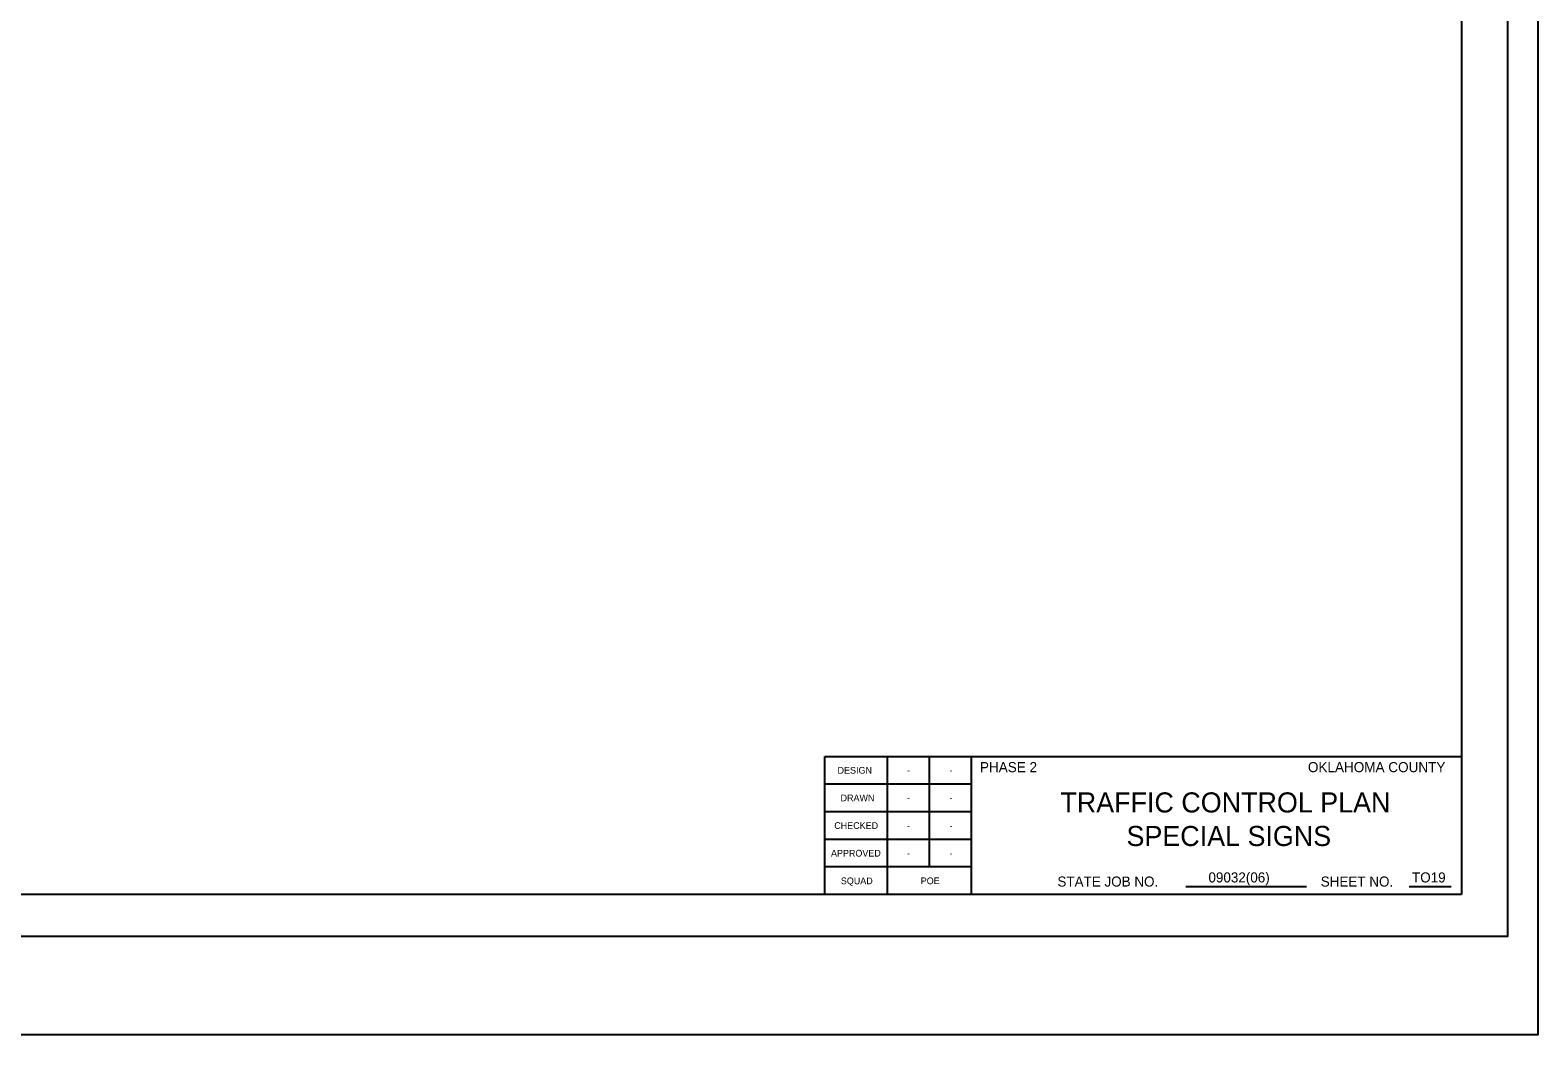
# Model space of a CAD drawing. Extents: x -434 to 1366, y -662 to 538.
# Drawn here: x 466 to 1366, y -662 to -62 of the extents above; entities that cross this region are included whole.
import ezdxf

# ---------------------------------------------------------------- set-up
doc = ezdxf.new("R2010")
doc.units = 0
for name, color, linetype in [('SHT_Plot_Shape_Full', 7, 'Continuous'), ('SHT_Plot_Shape_Half', 7, 'Continuous'), ('SHT_Sheet_Border', 7, 'Continuous'), ('SHT_Standard_Sheet_Lines', 7, 'Continuous'), ('SHT_Standard_Sheet_Txt', 7, 'Continuous')]:
    doc.layers.add(name, color=color, linetype=linetype)

msp = doc.modelspace()

# ---------------------------------------------------------------- linework, layer by layer
at = {"layer": 'SHT_Plot_Shape_Full'}
msp.add_lwpolyline([(-433.98, 538.27), (1366.02, 538.27), (1366.02, -661.73), (-433.98, -661.73)], close=True, dxfattribs=at)
at = {"layer": 'SHT_Plot_Shape_Half'}
msp.add_lwpolyline([(-352.1, 497.02), (1347.9, 497.02), (1347.9, -602.98), (-352.1, -602.98)], close=True, dxfattribs=at)
at = {"layer": 'SHT_Sheet_Border'}
for p, q in [((940.4, -495.48), (1320.4, -495.47)), ((940.4, -577.98), (940.4, -495.48)), ((1027.89, -577.98), (1027.89, -495.44))]:
    msp.add_line(p, q, dxfattribs=at)
msp.add_lwpolyline([(1320.4, -577.98), (-254.6, -577.98), (-254.6, 472.02), (1320.4, 472.02)], close=True, dxfattribs=at)
at = {"layer": 'SHT_Standard_Sheet_Lines'}
for p, q in [((977.9, -577.98), (977.9, -495.44)), ((1002.89, -561.47), (1002.89, -495.44)), ((1155.93, -573.17), (1227.95, -573.17)), ((1289.17, -573.17), (1314.29, -573.17))]:
    msp.add_line(p, q, dxfattribs=at)
for points in [[(1027.89, -511.98), (940.4, -511.98)], [(1027.89, -528.48), (940.4, -528.48)], [(1027.89, -544.98), (940.4, -544.98)], [(1027.89, -561.48), (940.4, -561.48)]]:
    msp.add_lwpolyline(points, dxfattribs=at)

# ---------------------------------------------------------------- texts
at = {"layer": 'SHT_Standard_Sheet_Txt'}
for s, height, p in [('DESIGN', 4, (948.01, -505.73)), ('-', 4, (989.42, -505.71)), ('-', 4, (1014.84, -505.71)), ('DRAWN', 4, (949.8, -522.23)), ('-', 4, (989.42, -522.21)), ('-', 4, (1014.84, -522.21)), ('TRAFFIC CONTROL PLAN', 12, (1081, -528.93)), ('CHECKED', 4, (946.04, -538.74)), ('-', 4, (989.42, -538.72)), ('-', 4, (1014.84, -538.72)), ('SPECIAL SIGNS', 12, (1120.47, -548.97)), ('APPROVED', 4, (944.08, -555.25)), ('-', 4, (989.42, -555.23)), ('-', 4, (1014.84, -555.23)), ('09032(06)', 6, (1169.4, -570.71)), ('TO19', 6, (1290.91, -570.71)), ('SQUAD', 4, (949.97, -571.76)), ('POE', 4, (997.65, -571.73)), ('STATE JOB NO.', 6, (1079.25, -573.17)), ('SHEET NO. ', 6, (1236.43, -573.17))]:
    msp.add_text(s, height=height, dxfattribs=at).set_placement(p)
for s, height, p in [('PHASE 2', 6.035, (1033, -504.86)), ('OKLAHOMA COUNTY', 6.0352, (1228.77, -504.86))]:
    msp.add_text(s, height=height, rotation=0, dxfattribs=at).set_placement(p)

doc.saveas('drawing.dxf')
